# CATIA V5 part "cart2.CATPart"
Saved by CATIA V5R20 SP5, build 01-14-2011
Part number: 连接柱
Material "Orange": density 7860 kg/m3, Young's modulus 2e+11 Pa, Poisson ratio 0.266
Bounding box of the stored display mesh (mm): x 0 to 10, y -6.929 to 6.929, z -6.756 to 36.756
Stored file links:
  E:\设计\180212313林恺昇\cart2.CATPart
  C:\Program Files\Dassault Systemes\B20\intel_a\startup\materials\Catalog.CATMaterial
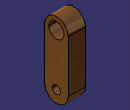
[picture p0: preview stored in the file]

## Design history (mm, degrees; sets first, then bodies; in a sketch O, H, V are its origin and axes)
Body1 (main body)
  Sketch1 on yz-plane, origin (0, 0, 0), H (0, 1, 0), V (0, 0, 1)
    construction line L1 (0, 0) -> (0, 30)
    point P1 (0, 30)
    line L2 (-6.9294, 0) -> (-6.9294, 30)
    line L3 (6.9294, 30) -> (6.9294, 0)
    arc A1 centre (0, 30) radius 6.9294 from (-6.9294, 30) to (6.9294, 30) cw
    arc A2 centre (0, 0) radius 6.9294 from (6.9294, 0) to (-6.9294, 0) cw
    circle A3 centre (0, 30) radius 4.5
    circle A4 centre (0, 0) radius 2.5
    point P6 (2.5, 0)
    distance L1 L2 = 6.9294
    radius A4 = 2.5
    radius A3 = 4.5
    distance P1 O = 30
    vertical: L1 V
    tangency: A1 L2, A2 L2, A1 L3, A2 L3
    coincidence: A4 P6, P6 H
  Pad1: profile Sketch1, direction (1, 0, 0), length 10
